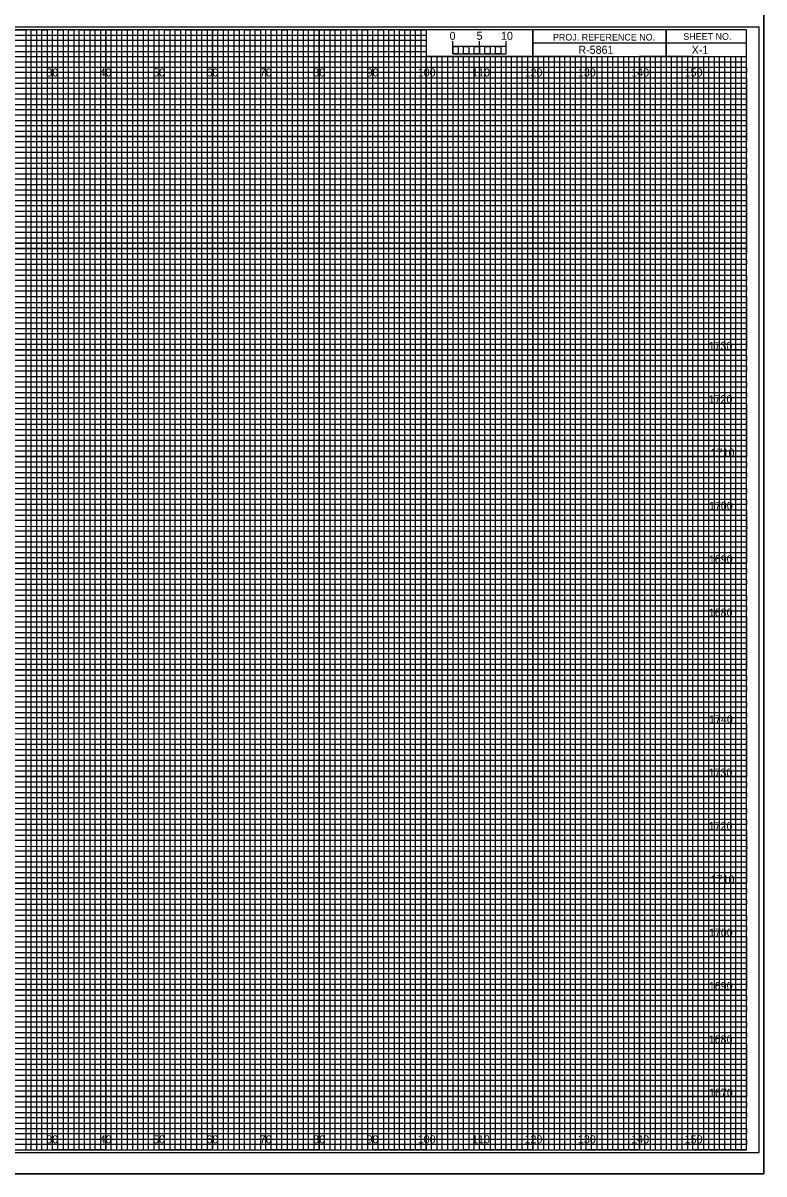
# Model space of a CAD drawing. Extents: x -419 to 4739, y -630 to 13534.
# Drawn here: x 184.5 to 323.3, y -4.5 to 211.3 of the extents above; entities that cross this region are included whole.
import ezdxf

# ---------------------------------------------------------------- set-up
doc = ezdxf.new("R2010")
doc.units = 0
for name, color, linetype in [('Old_Level_1', 7, 'Continuous'), ('Old_Level_62', 7, 'Continuous'), ('Pattern 1', 7, 'Continuous'), ('Pattern 18', 7, 'Continuous'), ('Pattern 4', 7, 'Continuous'), ('Pattern 5', 7, 'Continuous'), ('Prop Dimension', 7, 'Continuous'), ('Prop Horizontal Alignment', 7, 'Continuous'), ('Prop PHM Label Text', 7, 'Continuous'), ('Prop PHM Label Text White', 7, 'Continuous'), ('Prop PHM Roadway Shape', 7, 'Continuous'), ('Raster_Level_0', 7, 'Continuous'), ('Scratch_Level_0', 7, 'Continuous'), ('Scratch_Level_3', 7, 'Continuous'), ('Scratch_Level_5', 7, 'Continuous')]:
    doc.layers.add(name, color=color, linetype=linetype)

msp = doc.modelspace()

# ---------------------------------------------------------------- linework, layer by layer
at = {"layer": 'Old_Level_62'}
for p, q in [((305, 210), (305, 205)), ((305, 205), (305, 210)), ((280, 207.5), (280, 205)), ((320, 207.49), (280, 207.49)), ((280, 205), (320, 205))]:
    msp.add_line(p, q, dxfattribs=at)
for points in [[(320, 210), (0, 210), (0, 0), (320, 0)], [(280, 210), (260, 210), (260, 205.03), (280, 205.03)], [(320, 210), (280, 210), (280, 205), (320, 205)]]:
    msp.add_lwpolyline(points, close=True, dxfattribs=at)
at = {"layer": 'Pattern 18'}
for points in [[(-13.4, -4.5), (323.3, -4.5), (323.3, 214.5), (-13.4, 214.5)], [(-13.4, 214.5), (323.3, 214.5), (323.3, -4.5), (-13.4, -4.5)]]:
    msp.add_lwpolyline(points, close=True, dxfattribs=at)
at = {"layer": 'Pattern 4'}
for p, q in [((0, 209), (260, 209)), ((260, 207.98), (0, 207.98)), ((260, 209), (260, 207.98)), ((0, 207), (260, 207)), ((260, 205.89), (0, 205.89)), ((260, 207), (260, 205.89)), ((0, 204), (320, 204))]:
    msp.add_line(p, q, dxfattribs=at)
for points in [[(0, 203), (270, 203), (320, 203), (320, 202), (0, 202)], [(0, 201), (320, 201), (320, 199), (0, 199)], [(0, 198), (320, 198), (320, 197), (0, 196.98)], [(0, 196), (320, 196), (320, 194), (0, 194)], [(0, 193), (320, 193), (320, 192), (0, 192)], [(0, 191), (320, 191), (320, 189), (0, 189)], [(0, 188), (320, 188), (320, 187), (0, 187)], [(0, 186), (320, 186), (320, 184), (0, 184)], [(0, 183), (320, 183), (320, 182), (0, 182)], [(0, 181), (320, 181), (320, 179), (0, 179)], [(0, 178), (320, 178), (320, 177), (0, 177)], [(0, 176), (320, 176), (320, 173.95), (320, 173), (320, 172), (0, 172)], [(0, 174), (320, 174), (320, 173), (0, 173)], [(0, 171), (320, 171), (320, 169), (0, 169.03)], [(0, 169.03), (320, 169), (320, 168), (0, 168)], [(0, 167), (320, 167), (320, 166), (0, 166)], [(0, 164), (320, 164), (320, 163), (0, 163)], [(0, 162), (320, 162), (320, 161), (0, 161)], [(-0.07, 158.89), (320, 158.89), (320, 157.88), (-0.07, 157.88)], [(0, 157), (320, 157), (320, 156), (0, 156)], [(0, 154), (320, 154), (320, 153), (0, 153)], [(0, 152), (320, 152), (320, 151), (0, 151)], [(0, 149), (320, 149), (320, 148), (0, 148)], [(0, 147), (320, 147), (320, 146), (0, 146)], [(0, 144), (320, 144), (320, 143), (0, 143)], [(0, 142), (320, 142), (320, 141), (0, 141)], [(0, 139), (320, 139), (319.99, 137.98), (0, 138)], [(0, 137), (320, 137), (320, 136), (0, 136)], [(0, 134), (320, 134), (320, 133), (0, 133)], [(0, 132), (320, 132), (320, 131), (0, 131)], [(0, 129), (320, 129), (320, 128), (0, 128)], [(0, 127), (320, 127), (320, 126), (0, 126)], [(0, 124), (320, 124), (320, 123), (0, 123)], [(0, 122), (320, 122), (320, 121), (0, 121)], [(0, 119), (320, 119), (320, 118), (0, 118)], [(0, 116.99), (320.07, 116.91), (320, 116), (0, 116)], [(0, 114), (320, 114), (320, 113), (0, 113)], [(0, 112), (320, 112), (320, 111), (0, 111)], [(0, 109), (320, 109), (320, 108), (0, 108)], [(0, 107), (320, 107), (320, 106), (0, 106)], [(0, 104), (320, 104), (320, 103), (0, 103)], [(0, 102), (320, 102), (320, 101), (0, 101)], [(0, 99), (320, 99), (320, 98), (0, 98)], [(0, 97), (320, 97), (320, 96), (0, 96)], [(0, 94), (320, 94), (320, 93), (0, 93)], [(0, 92), (320, 92), (320, 91), (0, 91)], [(0, 89), (320, 89), (320, 88), (0, 88)], [(0, 87), (320, 87), (320, 86), (0, 86)], [(0, 84), (320, 84), (320, 83), (0, 83)], [(0, 82), (320, 82), (320, 81), (0, 81)], [(0, 79), (320, 79), (319.99, 77.98), (0, 78)], [(0, 77), (320, 77), (320, 76), (0, 76)], [(0, 74), (320, 74), (320, 73), (0, 73)], [(0, 72), (320, 72), (320, 71), (0, 71)], [(0, 69), (320, 69), (320, 68), (0, 68)], [(0, 67), (320, 67), (320, 66), (0, 66)], [(0, 64), (320, 64), (320, 63), (0, 63)], [(0, 62), (320, 62), (320, 61), (0, 61)], [(0, 59), (320, 59), (320, 58), (0, 58)], [(0, 56.99), (320.07, 56.91), (320, 56), (0, 56)], [(0, 54), (320, 54), (320, 53), (0, 53)], [(0, 52), (320, 52), (320, 51), (0, 51)], [(0, 49), (320, 49), (320, 48), (0, 48)], [(0, 47), (320, 47), (320, 46), (0, 46)], [(0, 44), (320, 44), (320, 43), (0, 43)], [(0, 42), (320, 42), (320, 41), (0, 41)], [(0, 39), (320, 39), (320, 38), (0, 38)], [(0, 37), (320, 37), (320, 36), (0, 36)], [(0, 34), (320, 34), (320, 33), (0, 33)], [(0, 32), (320, 32), (320, 31), (0, 31)], [(0, 29), (320, 29), (320, 28), (0, 28)], [(0, 27), (320, 27), (320, 26), (0, 26)], [(0, 24), (320, 24), (320, 23), (0, 23)], [(0, 22), (320, 22), (320, 21), (0, 21)], [(0, 19), (320, 19), (320, 18), (0, 18)], [(0, 17), (320, 17), (320, 16), (0, 16)], [(0, 14), (320, 14), (320, 13), (0, 13)], [(0, 12), (320, 12), (320, 11), (0, 11)], [(0, 9), (320, 9), (320, 8), (0, 8)], [(0, 7), (320, 7), (320, 6), (0, 6)], [(0, 4), (320, 4), (320, 3), (0, 3)], [(0, 2), (320, 2), (320, 1), (0, 1)]]:
    msp.add_lwpolyline(points, dxfattribs=at)
at = {"layer": 'Pattern 5'}
msp.add_line((-13.4, -4.5), (323.3, -4.5), dxfattribs=at)
at = {"layer": 'Prop Dimension'}
for p, q in [((267, 205), (266.01, 205)), ((266.01, 205), (266.01, 0)), ((267, 0), (267, 205)), ((269, 205), (268, 205)), ((268, 205), (268, 0)), ((269, 0), (269, 205)), ((266.01, 0), (265, 0)), ((268, 0), (267, 0))]:
    msp.add_line(p, q, dxfattribs=at)
for points in [[(185, 0), (186, 0), (186, 210), (187, 210), (187, 0)], [(187, 0), (188, 0), (188, 210), (189, 210), (189, 0)], [(190, 0), (191, 0), (191, 210), (192, 210), (192, 0)], [(192, 0), (193, 0), (193, 210), (194, 210), (194, 0)], [(195, 0), (196, 0), (196, 210), (197, 210), (197, 0)], [(197, 0), (198, 0), (198, 210), (199, 210), (199, 0)], [(200, 0), (201, 0), (201, 210), (202, 210), (202, 0)], [(202, 0), (203, 0), (203, 210), (204, 210), (204, 0)], [(205, 0), (206, 0), (206, 210), (207, 210), (207, 0)], [(207, 0), (208, 0), (208, 210), (209, 210), (209, 0)], [(210, 0), (211, 0), (211, 210), (212, 210), (212, 0)], [(212, 0), (213, 0), (213, 210), (214, 210), (214, 0)], [(215, 0), (216, 0), (216, 210), (217, 210), (217, 0)], [(217, 0), (218, 0), (218, 210), (219, 210), (219, 0)], [(220, 0), (221, 0), (221, 210), (222, 210), (222, 0)], [(222, 0), (223, 0), (223, 210), (224, 210), (224, 0)], [(225, 0), (226, 0), (226, 210), (227, 210), (227, 0)], [(227, 0), (228, 0), (228, 210), (229, 210), (229, 0)], [(230, 0), (231, 0), (231, 210), (232, 210), (232, 0)], [(232, 0), (233, 0), (233, 210), (234, 210), (234, 0)], [(235, 0), (236, 0), (236, 210), (237, 210), (237, 0)], [(237, 0), (238, 0), (238, 210), (239, 210), (239, 0)], [(240, 0), (241, 0), (241, 210), (242, 210), (242, 0)], [(242, 0), (243, 0), (243, 210), (244, 210), (244, 0)], [(245, 0), (246, 0), (246, 210), (247, 210), (247, 0)], [(247, 0), (248, 0), (248, 210), (249, 210), (249, 0)], [(250, 0), (251, 0), (251, 210), (252, 210), (252, 0)], [(252, 0), (253, 0), (253, 210), (254, 210), (254, 0)], [(255, 0), (256, 0), (256, 210), (257, 210), (257, 0)], [(257, 0), (258, 0), (258, 210), (259, 210), (259, 0)], [(260, 0), (261, 0), (261, 205), (262.02, 205), (262.02, 0)], [(262, 0), (263, 0), (263, 205), (263.99, 205), (263.99, 0)], [(270, 0), (270.98, 0), (270.98, 205), (272, 205), (272, 0)], [(272, 0), (273, 0), (273, 205), (274.05, 205), (274.05, 0)], [(275, 0), (276, 0), (276, 205), (277, 205), (277, 0)], [(277, 0), (278, 0), (278, 205), (279, 205), (279, 0)], [(280, 0), (281, 0), (281, 205), (282, 205), (282, 0)], [(282, 0), (283, 0), (283, 205), (284, 205), (284, 0)], [(285, 0), (286, 0), (286, 205), (287, 205), (287, 0)], [(287, 0), (288, 0), (288, 205), (289, 205), (289, 0)], [(290, 0), (291, 0), (291, 205), (292, 205), (292, 0)], [(292, 0), (293, 0), (293, 205), (294, 205), (294, 0)], [(295, 0), (296, 0), (296, 205), (297, 205), (297, 0)], [(297, 0), (298, 0), (298, 205), (299, 205), (299, 0)], [(300, 0), (301, 0), (301, 205), (302, 205), (302, 0)], [(302, 0), (303, 0), (303, 205), (304, 205), (304, 0)], [(305, 0), (306, 0), (306, 205), (307, 205), (307, 0)], [(307, 0), (308, 0), (308, 205), (309, 205), (309, 0)], [(310, 0), (311, 0), (311, 205), (312, 205), (312, 0)], [(312, 0), (313, 0), (313, 205), (314, 205), (314, 0)], [(315, 0), (316, 0), (316, 205), (317, 205), (317, 0)], [(317, 0), (318, 0), (318, 205), (319, 205), (319, 0)]]:
    msp.add_lwpolyline(points, dxfattribs=at)
at = {"layer": 'Prop Horizontal Alignment'}
for points in [[(175, 210), (185, 210), (185, 0), (195, 0), (195, 210), (205, 210), (205, 0), (215, 0), (215, 210), (225, 210), (225, 0), (235, 0), (235, 210), (245, 210), (245, 0), (255, 0), (255, 210), (259.93, 210), (260, 210), (260, 205), (264.99, 205), (264.99, 0), (275, 0), (275, 205), (285, 205), (285, 0), (295, 0), (295, 205), (305, 205), (305, 0), (315, 0), (315, 205)], [(0, 205), (275, 205)], [(0, 185), (320, 185), (320, 195), (0, 195)], [(0, 165), (320, 165), (320, 175), (0, 175)], [(0, 145), (320, 145), (320, 155), (0, 155)], [(0, 125), (320, 125), (320, 135), (0, 135)], [(0, 105), (320, 105), (320, 115), (0, 115)], [(0, 85), (320, 85), (320, 95), (0, 95)], [(0, 65), (320, 65), (320, 75), (0, 75)], [(0, 45), (320, 45), (320, 55), (0, 55)], [(0, 25), (320, 25), (320, 35), (0, 35)], [(0, 5), (320, 5), (320, 15), (0, 15)]]:
    msp.add_lwpolyline(points, dxfattribs=at)
at = {"layer": 'Prop PHM Label Text'}
for p, q in [((265, 205.49), (265, 207.9)), ((265, 206.9), (265, 207.9)), ((270, 205.49), (270, 207.9)), ((275, 205.49), (275, 207.9)), ((275, 206.9), (275, 207.9))]:
    msp.add_line(p, q, dxfattribs=at)
for points in [[(275, 206.9), (265, 206.9), (265, 205.49), (275, 205.49)], [(265, 206.9), (266, 206.9), (266, 205.49), (265, 205.49)], [(267, 206.9), (268, 206.9), (268, 205.49), (267, 205.49)], [(269, 206.9), (270, 206.9), (270, 205.49), (269, 205.49)], [(271, 206.9), (272, 206.9), (272, 205.49), (271, 205.49)], [(273, 206.9), (274, 206.9), (274, 205.49), (273, 205.49)]]:
    msp.add_lwpolyline(points, close=True, dxfattribs=at)
at = {"layer": 'Scratch_Level_0'}
for p, q in [((190, 0), (190, 210)), ((200, 0), (200, 210)), ((210, 0), (210, 210)), ((220, 0), (220, 210)), ((230, 0), (230, 210)), ((240, 0), (240, 210)), ((250, 0), (250, 210)), ((260, 0), (260, 204.69)), ((270, 0), (270, 204.69)), ((280, 0), (280, 204.69)), ((290, 0), (290, 204.69)), ((300, 0), (300, 204.69)), ((310, 0), (310, 204.69)), ((0, 200), (320, 200)), ((0, 190), (320, 190)), ((0, 180), (320, 180)), ((0, 170), (320, 170)), ((0, 160), (320, 160)), ((0, 150), (320, 150)), ((0, 140), (320, 140)), ((0, 130), (320, 130)), ((0, 120), (320, 120)), ((0, 110), (320, 110)), ((0, 100), (320, 100)), ((0, 90), (320, 90)), ((0, 80), (320, 80)), ((0, 70), (320, 70)), ((0, 60), (320, 60)), ((0, 50), (320, 50)), ((0, 40), (320, 40)), ((0, 30), (320, 30)), ((0, 20), (320, 20)), ((0, 10), (320, 10))]:
    msp.add_line(p, q, dxfattribs=at)
at = {"layer": 'Scratch_Level_3'}
for p, q in [((190, 210), (180, 210)), ((190, 0), (190, 210)), ((210, 210), (200, 210)), ((200, 210), (200, 0)), ((210, 0), (210, 210)), ((230, 210), (220, 210)), ((220, 210), (220, 0)), ((230, 0), (230, 210)), ((250, 210), (240, 210)), ((240, 210), (240, 0)), ((250, 0), (250, 210)), ((260, 210), (260, 0)), ((270, 0), (270, 205)), ((290, 205), (280, 205)), ((280, 205), (280, 0)), ((290, 0), (290, 205)), ((310, 205), (300, 205)), ((300, 205), (300, 0)), ((310, 0), (310, 205)), ((200, 0), (190, 0)), ((220, 0), (210, 0)), ((240, 0), (230, 0)), ((260, 0), (250, 0)), ((280, 0), (270, 0)), ((300, 0), (290, 0)), ((320, 0), (310, 0)), ((320, 0), (320, 0))]:
    msp.add_line(p, q, dxfattribs=at)
for points in [[(0, 200), (320, 200), (320, 190), (0, 190)], [(0, 180), (320, 180), (320, 170), (0, 170)], [(0, 160), (320, 160), (320, 150), (0, 150)], [(0, 140), (320, 140), (320, 130), (0, 130)], [(0, 120), (320, 120), (320, 110), (0, 110)], [(0, 100), (320, 100), (320, 90), (0, 90)], [(0, 80), (320, 80), (320, 70), (0, 70)], [(0, 60), (320, 60), (320, 50), (0, 50)], [(0, 40), (320, 40), (320, 30), (0, 30)], [(0, 20), (320, 20), (320, 10), (0, 10)]]:
    msp.add_lwpolyline(points, dxfattribs=at)
at = {"layer": 'Scratch_Level_5'}
msp.add_lwpolyline([(-10.8, -0.5), (322.4, -0.5), (322.4, 210.5), (-10.8, 210.5)], close=True, dxfattribs=at)

# ---------------------------------------------------------------- texts
at = {"layer": 'Old_Level_1'}
for s, p in [('5', (269.47, 208.12)), ('10', (274.04, 208.12))]:
    msp.add_text(s, height=1.5, dxfattribs=at).set_placement(p)
at = {"layer": 'Old_Level_62'}
for s, p in [('SHEET NO.', (308.19, 208.12)), ('PROJ. REFERENCE NO.', (283.77, 207.99))]:
    msp.add_text(s, height=1.25, dxfattribs=at).set_placement(p)
at = {"layer": 'Pattern 1'}
for s, p in [('1730', (312.92, 150)), ('1720', (312.93, 140)), ('1710', (313.31, 130)), ('1700', (312.98, 120)), ('1690', (312.97, 110)), ('1680', (312.95, 100)), ('1740', (313, 80)), ('1730', (312.92, 70)), ('1720', (312.93, 60)), ('1710', (313.31, 50)), ('1700', (312.98, 40)), ('1690', (312.97, 30)), ('1680', (312.95, 20)), ('1670', (313, 10))]:
    msp.add_text(s, height=1.5, dxfattribs=at).set_placement(p)
at = {"layer": 'Prop PHM Label Text'}
msp.add_text('0', height=1.5, dxfattribs=at).set_placement((264.41, 208.12))
at = {"layer": 'Prop PHM Label Text White'}
msp.add_text('X-1', height=1.5, dxfattribs=at).set_placement((309.76, 205.5))
at = {"layer": 'Prop PHM Roadway Shape'}
msp.add_text('R-5861', height=1.5, dxfattribs=at).set_placement((288.53, 205.5))
at = {"layer": 'Raster_Level_0'}
for s, p in [('30', (188.86, 201.25)), ('40', (198.86, 201.25)), ('50', (208.86, 201.25)), ('60', (218.86, 201.25)), ('70', (228.86, 201.25)), ('80', (238.86, 201.25)), ('90', (248.86, 201.25)), ('100', (258.44, 201.25)), ('110', (268.62, 201.25)), ('120', (278.44, 201.25)), ('130', (288.44, 201.25)), ('140', (298.44, 201.25)), ('150', (308.44, 201.25)), ('30', (188.86, 1.25)), ('40', (198.86, 1.25)), ('50', (208.86, 1.25)), ('60', (218.86, 1.25)), ('70', (228.86, 1.25)), ('80', (238.86, 1.25)), ('90', (248.86, 1.25)), ('100', (258.44, 1.25)), ('110', (268.62, 1.25)), ('120', (278.44, 1.25)), ('130', (288.44, 1.25)), ('140', (298.44, 1.25)), ('150', (308.44, 1.25))]:
    msp.add_text(s, height=1.5, dxfattribs=at).set_placement(p)

doc.saveas('drawing.dxf')
